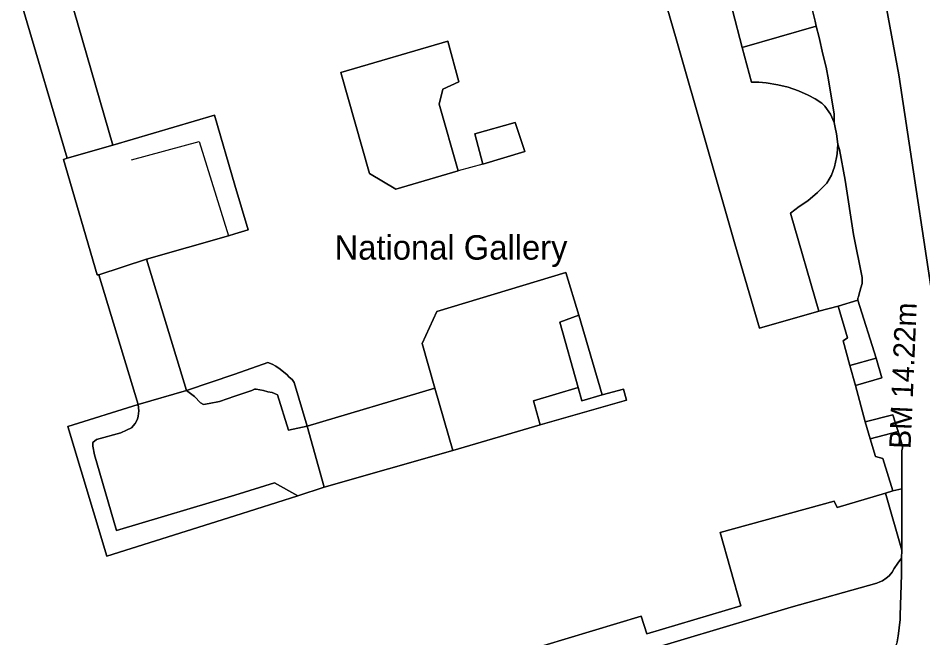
# Model space of a CAD drawing. Extents: x 529240 to 530363, y 179600 to 180767.
# Drawn here: x 529982.3 to 530056.2, y 180532 to 180582.7 of the extents above; entities that cross this region are included whole.
import ezdxf

# ---------------------------------------------------------------- set-up
doc = ezdxf.new("R2010")
doc.units = 0
for name, color, linetype in [('Building', 7, 'Continuous'), ('General surface', 7, 'Continuous'), ('Road Or Track', 7, 'Continuous'), ('Roadside', 7, 'Continuous'), ('Unclassified', 7, 'Continuous')]:
    doc.layers.add(name, color=color, linetype=linetype)

msp = doc.modelspace()

# ---------------------------------------------------------------- linework, layer by layer
at = {"layer": 'Building'}
for points in [[(530028.35, 180598.5), (530031.05, 180598.25), (530036.05, 180580.95), (530040.85, 180564.2), (530042.85, 180557.3), (530047.7, 180558.7)], [(530023.25, 180530.75), (530033.2, 180533.75), (530033.65, 180532.3), (530041.35, 180534.6), (530039.65, 180540.6), (530048.95, 180543.15), (530049.2, 180542.65), (530053.15, 180543.8), (530053.75, 180544), (530052.95, 180546.65), (530052.35, 180546.8), (530051.9, 180548.25), (530051.5, 180549.65), (530050.7, 180552.6), (530050.25, 180554.25), (530049.7, 180556.25), (530050.05, 180556.5), (530049.3, 180559.1), (530047.7, 180558.7), (530042.85, 180557.3), (530040.85, 180564.2), (530036.05, 180580.95), (530031.05, 180598.25)], [(530031.05, 180598.25), (530036.05, 180580.95), (530040.85, 180564.2), (530042.85, 180557.3), (530047.7, 180558.7), (530045.4, 180566.7), (530046.1, 180567.25), (530046.8, 180567.7), (530047.6, 180568.4), (530048.35, 180569.15), (530048.75, 180569.8), (530049, 180570.5), (530049.15, 180571.25), (530049.2, 180571.55), (530049.25, 180572.35), (530049.15, 180573.2), (530049.05, 180573.7), (530048.95, 180574.1), (530048.65, 180574.8), (530048.2, 180575.45), (530047.95, 180575.7), (530047.4, 180576.05), (530046.85, 180576.35), (530046.05, 180576.7), (530045.2, 180577), (530044.35, 180577.2), (530043.4, 180577.35), (530042.8, 180577.4), (530042.2, 180577.4), (530041.45, 180580.25), (530040.65, 180583.3)], [(529990.05, 180572.25), (529986.5, 180584.55), (529986.13, 180585.9)], [(529982.3, 180584.8), (529982.7, 180583.45), (529986.3, 180571.2)], [(529986.5, 180584.55), (529990.05, 180572.25), (529998.35, 180574.7), (530000, 180569), (530001.1, 180565.35), (530000, 180565), (529999.5, 180564.85), (529992.8, 180562.95), (529996.05, 180552.2), (530000, 180553.55), (530002.7, 180554.5), (530003.05, 180554.35), (530003.35, 180554.2), (530003.7, 180553.95), (530004, 180553.7), (530004.25, 180553.5), (530004.45, 180553.3), (530004.7, 180553.1), (530004.85, 180552.85), (530005.9, 180549.3), (530016.35, 180552.4), (530015.3, 180556.05), (530016.5, 180558.65), (530027.05, 180561.85), (530028.1, 180558.35), (530030, 180551.85), (530031.75, 180552.3), (530032, 180551.4), (530024.95, 180549.4), (530017.8, 180547.3), (530007.3, 180544.3), (530005.15, 180543.6), (530000, 180541.95), (529989.55, 180538.65), (529986.35, 180549.25), (529992.1, 180551.05), (529988.9, 180561.65), (529988.75, 180561.65), (529986, 180571.1), (529986.3, 180571.2), (529982.7, 180583.45)], [(530040.65, 180583.3), (530041.45, 180580.25)], [(530018.25, 180570.15), (530013.15, 180568.65), (530011, 180569.95), (530008.65, 180578.2), (530017.4, 180580.75), (530018.3, 180577.45), (530017, 180576.85), (530016.7, 180575.6), (530018.25, 180570.15)], [(530041.45, 180580.25), (530042.2, 180577.4), (530042.8, 180577.4), (530043.4, 180577.35), (530044.35, 180577.2), (530045.2, 180577), (530046.05, 180576.7), (530046.85, 180576.35), (530047.4, 180576.05), (530047.95, 180575.7), (530048.2, 180575.45), (530048.65, 180574.8), (530048.95, 180574.1)], [(529999.5, 180564.85), (530000, 180565), (530001.1, 180565.35), (530000, 180569), (529998.35, 180574.7), (529990.05, 180572.25)], [(530020.25, 180570.7), (530019.6, 180573.2), (530022.9, 180574.1), (530023.7, 180571.75), (530020.25, 180570.7)], [(530048.95, 180574.1), (530049.05, 180573.7), (530049.15, 180573.2), (530049.25, 180572.35)], [(529990.05, 180572.25), (529986.3, 180571.2)], [(530049.25, 180572.35), (530049.2, 180571.55), (530049.15, 180571.25), (530049, 180570.5), (530048.75, 180569.8), (530048.35, 180569.15), (530047.6, 180568.4), (530046.8, 180567.7), (530046.1, 180567.25), (530045.4, 180566.7), (530047.7, 180558.7)], [(529986.3, 180571.2), (529986, 180571.1), (529988.75, 180561.65), (529988.9, 180561.65)], [(529992.8, 180562.95), (529999.5, 180564.85)], [(529988.9, 180561.65), (529992.8, 180562.95)], [(529996.05, 180552.2), (529992.8, 180562.95)], [(529988.9, 180561.65), (529992.1, 180551.05)], [(530016.35, 180552.4), (530015.3, 180556.05), (530016.5, 180558.65), (530027.05, 180561.85), (530028.1, 180558.35)], [(530047.7, 180558.7), (530049.3, 180559.1)], [(530049.3, 180559.1), (530050.05, 180556.5), (530049.7, 180556.25), (530050.25, 180554.25)], [(530028.1, 180558.35), (530030, 180551.85)], [(530005.9, 180549.3), (530004.85, 180552.85), (530004.7, 180553.1), (530004.45, 180553.3), (530004.25, 180553.5), (530004, 180553.7), (530003.7, 180553.95), (530003.35, 180554.2), (530003.05, 180554.35), (530002.7, 180554.5), (530000, 180553.55), (529996.05, 180552.2)], [(530050.25, 180554.25), (530050.7, 180552.6)], [(530050.7, 180552.6), (530051.5, 180549.65)], [(529996.05, 180552.2), (529992.1, 180551.05)], [(530005.9, 180549.3), (530016.35, 180552.4)], [(530017.8, 180547.3), (530016.35, 180552.4)], [(530030, 180551.85), (530031.75, 180552.3), (530032, 180551.4), (530024.95, 180549.4)], [(529992.1, 180551.05), (529986.35, 180549.25), (529989.55, 180538.65), (530000, 180541.95), (530005.15, 180543.6)], [(530051.9, 180548.25), (530051.5, 180549.65)], [(530005.9, 180549.3), (530007.3, 180544.3)], [(530024.95, 180549.4), (530017.8, 180547.3)], [(530053.75, 180544), (530052.95, 180546.65), (530052.35, 180546.8), (530051.9, 180548.25)], [(530007.3, 180544.3), (530017.8, 180547.3)], [(530007.3, 180544.3), (530005.15, 180543.6)], [(530023.25, 180530.75), (530033.2, 180533.75), (530033.65, 180532.3), (530041.35, 180534.6), (530039.65, 180540.6), (530048.95, 180543.15), (530049.2, 180542.65), (530053.15, 180543.8)], [(530053.15, 180543.8), (530053.75, 180544)]]:
    msp.add_lwpolyline(points, dxfattribs=at)
for points in [[(529986.13, 180585.9), (529982.3, 180584.8), (529982.7, 180583.45), (529986.3, 180571.2), (529990.05, 180572.25), (529986.5, 180584.55)], [(530013.15, 180568.65), (530018.25, 180570.15), (530016.7, 180575.6), (530017, 180576.85), (530018.3, 180577.45), (530017.4, 180580.75), (530008.65, 180578.2), (530011, 180569.95)], [(530020.25, 180570.7), (530023.7, 180571.75), (530022.9, 180574.1), (530019.6, 180573.2)], [(530020.25, 180570.7), (530023.7, 180571.75), (530022.9, 180574.1), (530019.6, 180573.2)], [(529992.1, 180551.05), (529996.05, 180552.2), (529992.8, 180562.95), (529988.9, 180561.65)], [(530007.3, 180544.3), (530017.8, 180547.3), (530016.35, 180552.4), (530005.9, 180549.3)]]:
    msp.add_lwpolyline(points, close=True, dxfattribs=at)
at = {"layer": 'General surface'}
for points in [[(530041.45, 180580.25), (530047.5, 180582), (530047.4, 180582.4), (530047.15, 180583.5), (530046.9, 180584.55), (530046.9, 180584.95), (530040.65, 180583.3)], [(530048.95, 180574.1), (530048.95, 180574.8), (530048.5, 180577.6), (530048.3, 180578.65), (530048.05, 180579.7), (530047.75, 180581.05), (530047.5, 180582), (530041.45, 180580.25), (530042.2, 180577.4), (530042.8, 180577.4), (530043.4, 180577.35), (530044.35, 180577.2), (530045.2, 180577), (530046.05, 180576.7), (530046.85, 180576.35), (530047.4, 180576.05), (530047.95, 180575.7), (530048.2, 180575.45), (530048.65, 180574.8)], [(530018.25, 180570.15), (530016.7, 180575.6), (530017, 180576.85), (530018.3, 180577.45), (530017.4, 180580.75), (530008.65, 180578.2), (530011, 180569.95), (530013.15, 180568.65)], [(529990.05, 180572.25), (529986.3, 180571.2), (529986, 180571.1), (529988.75, 180561.65), (529988.9, 180561.65), (529992.8, 180562.95), (529999.5, 180564.85), (530000, 180565), (530001.1, 180565.35), (530000, 180569), (529998.35, 180574.7)], [(530049.3, 180559.1), (530050.9, 180559.6), (530050.9, 180559.75), (530050.95, 180559.85), (530051, 180560.1), (530051.05, 180560.3), (530051.15, 180560.6), (530051.25, 180560.95), (530051.25, 180561.45), (530050.55, 180564.95), (530049.85, 180569.4), (530049.4, 180571.9), (530049.25, 180572.35), (530049.2, 180571.55), (530049.15, 180571.25), (530049, 180570.5), (530048.75, 180569.8), (530048.35, 180569.15), (530047.6, 180568.4), (530046.8, 180567.7), (530046.1, 180567.25), (530045.4, 180566.7), (530047.7, 180558.7)], [(530028.1, 180558.35), (530027.05, 180561.85), (530016.5, 180558.65), (530015.3, 180556.05), (530016.35, 180552.4), (530017.8, 180547.3), (530024.95, 180549.4), (530024.4, 180551.35), (530028.05, 180552.45), (530026.55, 180557.8)], [(530050.25, 180554.25), (530052.4, 180554.85), (530050.9, 180559.6), (530049.3, 180559.1), (530050.05, 180556.5), (530049.7, 180556.25)], [(530028.05, 180552.45), (530028.35, 180551.35), (530030, 180551.85), (530028.1, 180558.35), (530026.55, 180557.8)], [(530050.7, 180552.6), (530052.85, 180553.25), (530052.4, 180554.85), (530050.25, 180554.25)], [(530005.9, 180549.3), (530004.85, 180552.85), (530004.7, 180553.1), (530004.45, 180553.3), (530004.25, 180553.5), (530004, 180553.7), (530003.7, 180553.95), (530003.35, 180554.2), (530003.05, 180554.35), (530002.7, 180554.5), (530000, 180553.55), (529996.05, 180552.2), (529996.7, 180551.7), (529997.2, 180551.2), (529997.45, 180551.05), (529997.9, 180551.15), (529998.75, 180551.3), (530000, 180551.75), (530001.4, 180552.2), (530001.6, 180552.3), (530001.75, 180552.3), (530002.35, 180552.2), (530002.7, 180552.1), (530003.05, 180552.05), (530003.25, 180551.95), (530003.5, 180551.85), (530004.4, 180548.95)], [(530005.15, 180543.6), (530007.3, 180544.3), (530005.9, 180549.3), (530004.4, 180548.95), (530003.5, 180551.85), (530003.25, 180551.95), (530003.05, 180552.05), (530002.7, 180552.1), (530002.35, 180552.2), (530001.75, 180552.3), (530001.6, 180552.3), (530001.4, 180552.2), (530000, 180551.75), (529998.75, 180551.3), (529997.9, 180551.15), (529997.45, 180551.05), (529997.2, 180551.2), (529996.7, 180551.7), (529996.05, 180552.2), (529992.1, 180551.05), (529992.15, 180550.55), (529992.1, 180550.1), (529992.05, 180549.85), (529991.85, 180549.5), (529991.55, 180549.15), (529991.15, 180548.95), (529990.7, 180548.75), (529988.7, 180548.2), (529988.4, 180547.95), (529988.4, 180547.65), (529988.55, 180546.95), (529990.35, 180540.75), (530000, 180543.65), (530003.25, 180544.65)], [(530024.95, 180549.4), (530032, 180551.4), (530031.75, 180552.3), (530030, 180551.85), (530028.35, 180551.35), (530028.05, 180552.45), (530024.4, 180551.35)], [(529992.1, 180551.05), (529986.35, 180549.25), (529989.55, 180538.65), (530000, 180541.95), (530005.15, 180543.6), (530003.25, 180544.65), (530000, 180543.65), (529990.35, 180540.75), (529988.55, 180546.95), (529988.4, 180547.65), (529988.4, 180547.95), (529988.7, 180548.2), (529990.7, 180548.75), (529991.15, 180548.95), (529991.55, 180549.15), (529991.85, 180549.5), (529992.05, 180549.85), (529992.1, 180550.1), (529992.15, 180550.55)], [(530054.2, 180548.85), (530053.75, 180550.2), (530051.5, 180549.65), (530051.9, 180548.25)], [(530051.9, 180548.25), (530052.35, 180546.8), (530052.95, 180546.65), (530053.75, 180544), (530054.5, 180544.15), (530054.5, 180547.3), (530054.55, 180547.5), (530054.55, 180547.65), (530054.5, 180547.85), (530054.3, 180548.55), (530054.2, 180548.85)], [(530024, 180528.15), (530033.8, 180531), (530045.45, 180534.5), (530052.45, 180536.45), (530052.7, 180536.55), (530052.9, 180536.65), (530053.2, 180536.85), (530053.45, 180537.05), (530053.7, 180537.35), (530053.85, 180537.65), (530054.15, 180538.1), (530054.45, 180538.5), (530054.5, 180539.15), (530053.15, 180543.8), (530049.2, 180542.65), (530048.95, 180543.15), (530039.65, 180540.6), (530041.35, 180534.6), (530033.65, 180532.3), (530033.2, 180533.75), (530023.25, 180530.75)], [(530054.5, 180539.15), (530054.5, 180544.15), (530053.75, 180544), (530053.15, 180543.8)]]:
    msp.add_lwpolyline(points, close=True, dxfattribs=at)
msp.add_lwpolyline([(530054.1, 180531.65), (530054.2, 180532.15), (530054.25, 180532.55), (530054.3, 180533.05), (530054.35, 180533.45), (530054.35, 180533.8), (530054.45, 180537.15), (530054.45, 180538.5), (530054.15, 180538.1), (530053.85, 180537.65), (530053.7, 180537.35), (530053.45, 180537.05), (530053.2, 180536.85), (530052.9, 180536.65), (530052.7, 180536.55), (530052.45, 180536.45), (530045.45, 180534.5), (530033.8, 180531)], dxfattribs=at)
at = {"layer": 'Road Or Track'}
for points in [[(530056.95, 180608.24), (530055.43, 180611.51), (530053.879, 180614), (530038.318, 180614), (530038.8, 180613.61), (530039.13, 180613.28), (530041.57, 180610.87), (530044.05, 180607.86), (530046.21, 180604.61), (530048.02, 180601.16), (530049.57, 180597.24), (530051.5, 180590.93), (530051.81, 180589.64), (530052.74, 180585.85), (530053.06, 180584.52), (530054.24, 180578.02), (530057.7, 180555.12)], [(530038.318, 180614), (530038.8, 180613.61), (530039.13, 180613.28), (530041.57, 180610.87), (530044.05, 180607.86), (530046.21, 180604.61), (530048.02, 180601.16), (530049.57, 180597.24), (530051.5, 180590.93), (530051.81, 180589.64), (530052.74, 180585.85), (530053.06, 180584.52), (530054.24, 180578.02), (530057.7, 180555.12), (530058.27, 180550.35), (530058.54, 180544.96), (530058.42, 180539.56), (530057.67, 180532.67), (530056.88, 180529.46), (530054.83, 180522.81), (530053.86, 180519.67), (530053.84, 180519.58), (530053.37, 180517.77), (530053.15, 180516.9)]]:
    msp.add_lwpolyline(points, dxfattribs=at)
at = {"layer": 'Roadside'}
for points in [[(530057.7, 180555.12), (530054.24, 180578.02), (530053.06, 180584.52)], [(530047.15, 180583.5), (530047.4, 180582.4), (530047.5, 180582), (530047.75, 180581.05), (530048.05, 180579.7), (530048.3, 180578.65), (530048.5, 180577.6), (530048.95, 180574.8), (530048.95, 180574.1), (530049.05, 180573.7), (530049.15, 180573.2), (530049.25, 180572.35), (530049.4, 180571.9), (530049.85, 180569.4), (530050.55, 180564.95), (530051.25, 180561.45), (530051.25, 180560.95), (530051.15, 180560.6), (530051.05, 180560.3), (530051, 180560.1), (530050.95, 180559.85), (530050.9, 180559.75), (530050.9, 180559.6), (530052.4, 180554.85), (530052.85, 180553.25), (530050.7, 180552.6), (530051.5, 180549.65), (530053.75, 180550.2), (530054.2, 180548.85), (530054.3, 180548.55), (530054.5, 180547.85), (530054.55, 180547.65), (530054.55, 180547.5), (530054.5, 180547.3), (530054.5, 180544.15), (530054.5, 180539.15), (530054.45, 180538.5), (530054.45, 180537.15), (530054.35, 180533.8), (530054.35, 180533.45), (530054.3, 180533.05), (530054.25, 180532.55), (530054.2, 180532.15), (530054.1, 180531.65)]]:
    msp.add_lwpolyline(points, dxfattribs=at)
at = {"layer": 'Unclassified'}
msp.add_line((530054.25, 180548.9), (530054.25, 180548.9), dxfattribs=at)
msp.add_line((530054.25, 180548.9), (530054.25, 180548.9), dxfattribs=at)
for points in [[(530046.9, 180584.95), (530046.9, 180584.55), (530047.15, 180583.5), (530047.4, 180582.4), (530047.5, 180582)], [(530041.45, 180580.25), (530047.5, 180582)], [(530047.5, 180582), (530047.75, 180581.05), (530048.05, 180579.7), (530048.3, 180578.65), (530048.5, 180577.6), (530048.95, 180574.8), (530048.95, 180574.1)], [(529991.55, 180571.05), (529997.1, 180572.55), (529999.5, 180564.85)], [(530049.25, 180572.35), (530049.4, 180571.9), (530049.85, 180569.4), (530050.55, 180564.95), (530051.25, 180561.45), (530051.25, 180560.95), (530051.15, 180560.6), (530051.05, 180560.3), (530051, 180560.1), (530050.95, 180559.85), (530050.9, 180559.75), (530050.9, 180559.6)], [(530020.25, 180570.7), (530018.25, 180570.15)], [(530049.3, 180559.1), (530050.9, 180559.6)], [(530050.9, 180559.6), (530052.4, 180554.85)], [(530028.1, 180558.35), (530026.55, 180557.8), (530028.05, 180552.45)], [(530050.25, 180554.25), (530052.4, 180554.85)], [(530052.4, 180554.85), (530052.85, 180553.25), (530050.7, 180552.6)], [(529996.05, 180552.2), (529996.7, 180551.7), (529997.2, 180551.2), (529997.45, 180551.05), (529997.9, 180551.15), (529998.75, 180551.3), (530000, 180551.75), (530001.4, 180552.2), (530001.6, 180552.3), (530001.75, 180552.3), (530002.35, 180552.2), (530002.7, 180552.1), (530003.05, 180552.05), (530003.25, 180551.95), (530003.5, 180551.85), (530004.4, 180548.95), (530005.9, 180549.3)], [(530024.95, 180549.4), (530024.4, 180551.35), (530028.05, 180552.45)], [(530028.05, 180552.45), (530028.35, 180551.35), (530030, 180551.85)], [(529992.1, 180551.05), (529992.15, 180550.55), (529992.1, 180550.1), (529992.05, 180549.85), (529991.85, 180549.5), (529991.55, 180549.15), (529991.15, 180548.95), (529990.7, 180548.75), (529988.7, 180548.2), (529988.4, 180547.95), (529988.4, 180547.65), (529988.55, 180546.95), (529990.35, 180540.75), (530000, 180543.65), (530003.25, 180544.65), (530005.15, 180543.6)], [(530051.5, 180549.65), (530053.75, 180550.2), (530054.2, 180548.85)], [(530051.9, 180548.25), (530054.2, 180548.85)], [(530054.2, 180548.85), (530054.3, 180548.55), (530054.5, 180547.85), (530054.55, 180547.65), (530054.55, 180547.5), (530054.5, 180547.3), (530054.5, 180544.15)], [(530053.15, 180543.8), (530054.5, 180539.15)], [(530053.75, 180544), (530054.5, 180544.15)], [(530054.5, 180544.15), (530054.5, 180539.15)], [(530024, 180528.15), (530033.8, 180531), (530045.45, 180534.5), (530052.45, 180536.45), (530052.7, 180536.55), (530052.9, 180536.65), (530053.2, 180536.85), (530053.45, 180537.05), (530053.7, 180537.35), (530053.85, 180537.65), (530054.15, 180538.1), (530054.45, 180538.5)], [(530054.45, 180538.5), (530054.45, 180537.15), (530054.35, 180533.8), (530054.35, 180533.45), (530054.3, 180533.05), (530054.25, 180532.55), (530054.2, 180532.15), (530054.1, 180531.65), (530053.95, 180531.2)], [(530054.5, 180539.15), (530054.45, 180538.5)]]:
    msp.add_lwpolyline(points, dxfattribs=at)

# ---------------------------------------------------------------- texts
msp.add_text('National Gallery', height=2, dxfattribs=at).set_placement((530008.15, 180562.9))
msp.add_text('BM 14.22m', height=1.75, rotation=87.5, dxfattribs=at).set_placement((530055.2, 180547.4))

doc.saveas('drawing.dxf')
